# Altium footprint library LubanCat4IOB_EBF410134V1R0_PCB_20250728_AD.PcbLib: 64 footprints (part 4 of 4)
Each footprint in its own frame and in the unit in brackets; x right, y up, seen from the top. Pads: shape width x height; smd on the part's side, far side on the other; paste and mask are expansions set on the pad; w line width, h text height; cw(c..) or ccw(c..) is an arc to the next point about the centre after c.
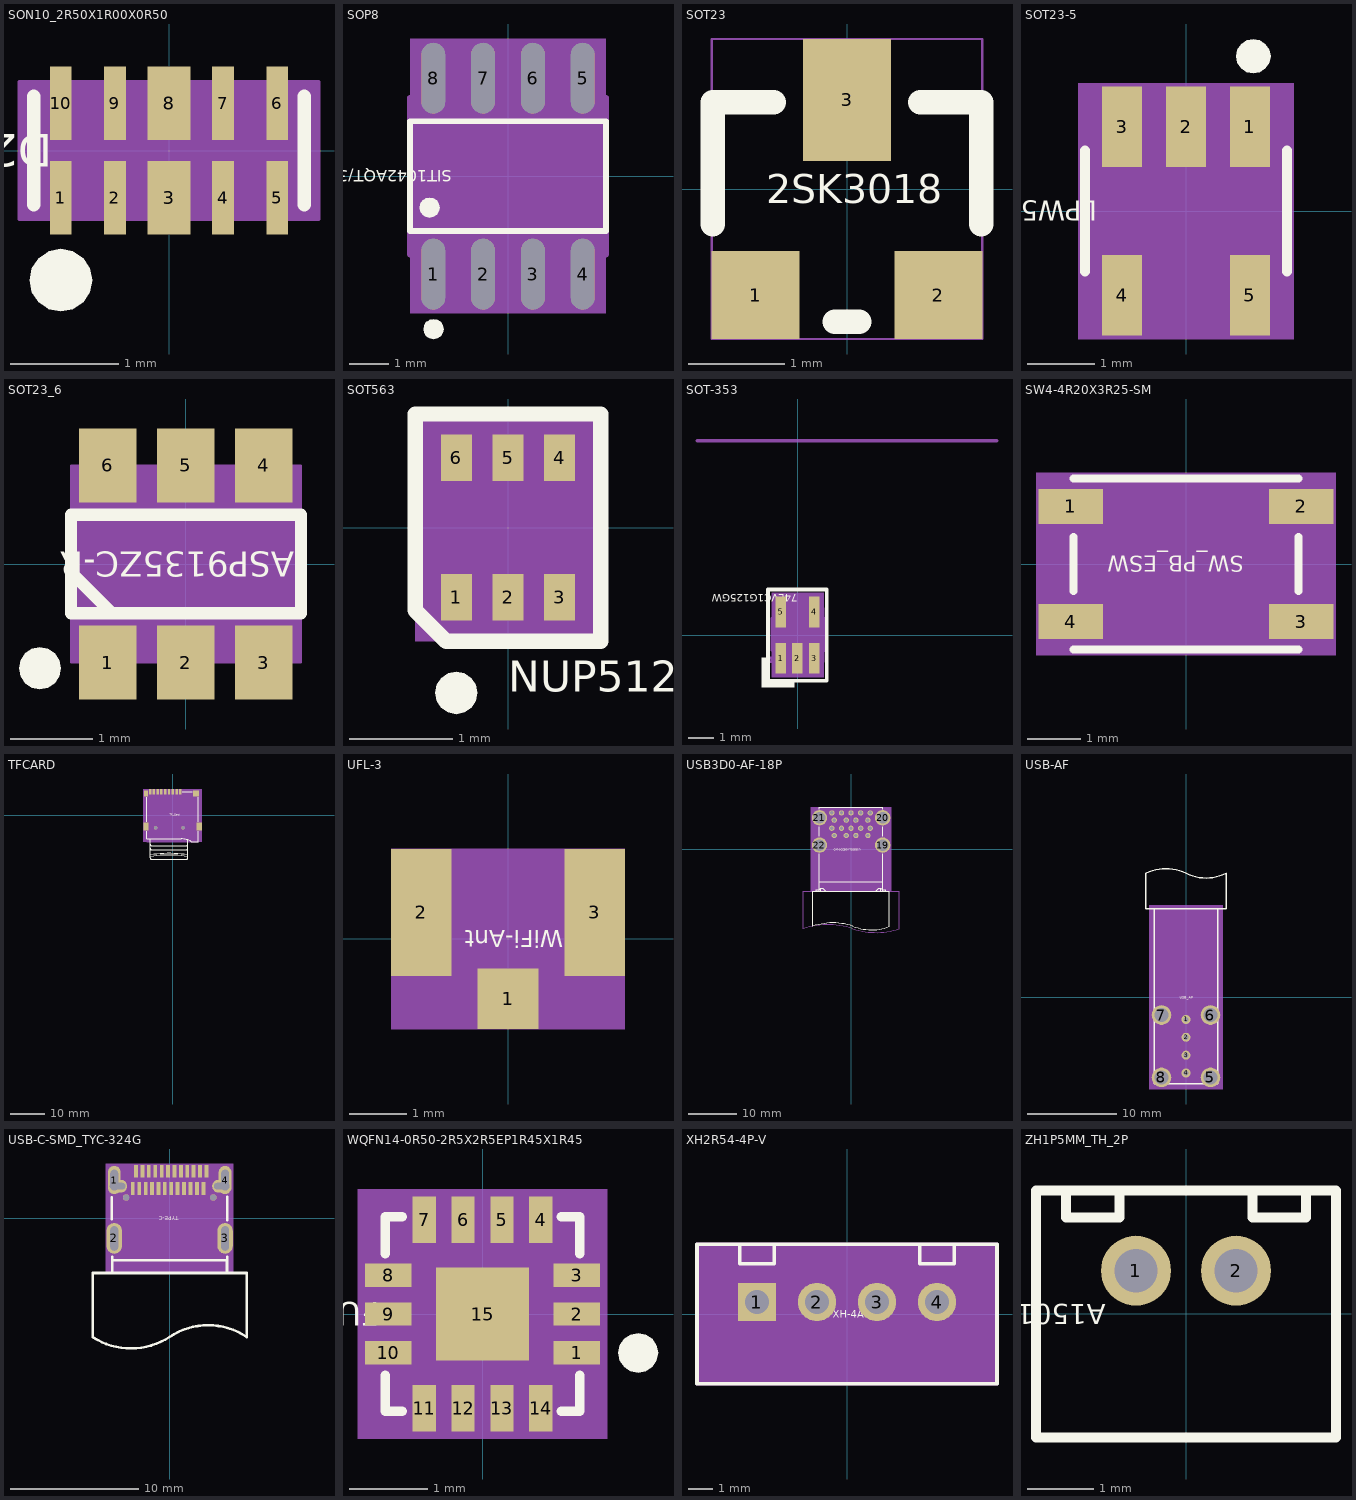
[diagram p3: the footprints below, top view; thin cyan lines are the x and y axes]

## SON10_2R50X1R00X0R50 [mm] "SON10_2R50X1R00X0R50"
pads (10):
  rect 0.2x0.68 smd: 1(-1,-0.437) 2(-0.5,-0.437) 4(0.5,-0.437) 5(1,-0.437) 6(1,0.437) 7(0.5,0.437) 9(-0.5,0.437) 10(-1,0.437)
  rect 0.4x0.68 smd: 3(0,-0.437) 8(0,0.437)
Top Overlay:
  dashed: -0.71,-1.199 -0.733,-1.31 -0.795,-1.404 -0.889,-1.467 -1,-1.489 -1.111,-1.467 -1.142,-1.446 -1.205,-1.404 -1.267,-1.31 -1.29,-1.199 -1.267,-1.089 -1.205,-0.995 -1.142,-0.953 -1.111,-0.932 -1,-0.91 -0.889,-0.932 -0.795,-0.995 -0.733,-1.089
  lines w0.127: -1.25,-0.5 -1.25,0.5 ; 1.25,-0.5 1.25,0.5
  text "D2550-3R3" at -1.08,0.15 h0.3
Top 3D Body:
  region: -1.388,-0.638 -1.388,0.638 1.388,0.638 1.388,-0.638
Mechanical 17:
  text "6" at 0.939,0.437 h0.15
  text "5" at 0.939,-0.437 h0.15
  text "4" at 0.439,-0.437 h0.15
  text "7" at 0.439,0.437 h0.15
  text "2" at -0.561,-0.437 h0.15
  text "9" at -0.561,0.437 h0.15
  text "1" at -1.061,-0.437 h0.15
  text "10" at -1.122,0.437 h0.15
  text "3" at -0.061,-0.437 h0.15
  text "8" at -0.061,0.437 h0.15
Top Assembly:
  lines w0.025: -1.388,-0.638 -1.388,0.638 1.388,0.638 1.388,-0.638 -1.388,-0.638
3D body: height 3.81, standoff 0, extent -1.388,-0.638 1.388,0.638

## SOP8 [mm] "SOP8"
pads (8):
  oval 0.6x1.8 smd: 1(-1.905,-2.5) 2(-0.635,-2.5) 3(0.635,-2.5) 4(1.905,-2.5) 5(1.905,2.5) 6(0.635,2.5) 7(-0.635,2.5) 8(-1.905,2.5)
Top Overlay:
  dashed: -1.645,-3.9 -1.665,-3.998 -1.72,-4.08 -1.802,-4.135 -1.9,-4.155 -1.998,-4.135 -2.025,-4.117 -2.08,-4.08 -2.135,-3.998 -2.155,-3.9 -2.135,-3.802 -2.08,-3.72 -2.025,-3.683 -1.998,-3.665 -1.9,-3.645 -1.802,-3.665 -1.72,-3.72 -1.665,-3.802
  dashed: -1.745,-0.8 -1.765,-0.898 -1.82,-0.98 -1.902,-1.035 -2,-1.055 -2.098,-1.035 -2.125,-1.017 -2.18,-0.98 -2.235,-0.898 -2.255,-0.8 -2.235,-0.702 -2.18,-0.62 -2.125,-0.583 -2.098,-0.565 -2,-0.545 -1.902,-0.565 -1.82,-0.62 -1.765,-0.702
  lines w0.15: -2.5,-1.4 2.5,-1.4 2.5,1.4 -2.5,1.4 -2.5,-1.4
  text "SIT1042AQT/3" at -1.44,0.15 h0.3
Top 3D Body:
  region: -2.5,3.5 -2.5,-3.5 2.5,-3.5 2.5,3.5
Mechanical 17:
  text "4" at 1.651,-2.5 h0.64
  text "1" at -2.159,-2.5 h0.64
  text "5" at 1.651,2.5 h0.64
  text "6" at 0.381,2.5 h0.64
  text "7" at -0.889,2.5 h0.64
  text "3" at 0.381,-2.5 h0.64
  text "2" at -0.889,-2.5 h0.64
  text "8" at -2.159,2.5 h0.64
Top Assembly:
  lines w0.15: -2.5,-2 2.5,-2 2.5,2 -2.5,2 -2.5,-2
3D body: height 3.81, standoff 0, extent -2.5,-3.5 2.5,3.5

## SOT23 [mil] "SOT23"
pads (3):
  rect 36x36 smd: 1(-37.5,-43.5) 2(37.5,-43.5)
  rect 36x50 smd: 3(0,36.5)
Top Overlay:
  lines w10: -55,-14.5 -55,35.5 -30,35.5 ; -5,-54.5 5,-54.5 ; 30,35.5 55,35.5 55,-14.5
  text "2SK3018" at -33.07,-5.91 h11.81
Top 3D Body:
  lines w1: -55.5,-61.5 55.5,-61.5 55.5,61.5 -55.5,61.5 -55.5,-61.5
Mechanical 17:
  text "3" at -18,36.5 h45
  text "1" at -55.5,-43.5 h45
  text "2" at 19.5,-43.5 h45

## SOT23-5 [mm] "SOT23-5"
pads (5):
  rect 0.599x1.199 smd: 1(0.95,1.25) 2(0,1.25) 3(-0.95,1.25) 4(-0.95,-1.25) 5(0.95,-1.25)
Top Overlay:
  dashed: 1.255,2.3 1.235,2.202 1.18,2.12 1.098,2.065 1,2.045 0.902,2.065 0.875,2.083 0.82,2.12 0.765,2.202 0.745,2.3 0.765,2.398 0.82,2.48 0.875,2.517 0.902,2.535 1,2.555 1.098,2.535 1.18,2.48 1.235,2.398
  lines w0.15: -1.5,-0.9 -1.5,0.9 ; 1.5,-0.9 1.5,0.9
  text "LPW5209AB5F" at -1.32,0.15 h0.3
Top 3D Body:
  region: 1.6,-1.9 1.6,1.9 -1.6,1.9 -1.6,-1.9
Mechanical 17:
  text "1" at 0.91,1.25 h0.1
  text "3" at -0.99,1.25 h0.1
  text "4" at -0.99,-1.25 h0.1
  text "2" at -0.04,1.25 h0.1
  text "5" at 0.91,-1.25 h0.1
Top Assembly:
  lines w0.15: -1.5,-0.85 -1.5,0.85 1.5,0.85 1.5,-0.85 -1.5,-0.85
3D body: height 3.81, standoff 0, extent -1.6,-1.9 1.6,1.9

## SOT23_6 [mm] "SOT23_6"
pads (6):
  rect 0.7x0.9 smd: 1(-0.95,-1.2) 2(0,-1.2) 3(0.95,-1.2) 4(0.95,1.2) 5(0,1.2) 6(-0.95,1.2)
Top Overlay:
  dashed: -2.033,-1.27 -2.014,-1.368 -1.958,-1.45 -1.876,-1.506 -1.778,-1.525 -1.68,-1.506 -1.653,-1.487 -1.598,-1.45 -1.542,-1.368 -1.523,-1.27 -1.542,-1.172 -1.598,-1.09 -1.653,-1.053 -1.68,-1.034 -1.778,-1.015 -1.876,-1.034 -1.958,-1.09 -2.014,-1.172
  lines w0.15: -1.4,-0.1 -0.9,-0.6 ; -1.4,-0.6 -1.4,0.6 1.4,0.6 1.4,-0.6 -1.4,-0.6
  text "ASP9135ZC-R" at 1.32,0.15 h0.3
Top 3D Body:
  region: -1.4,-1.2 1.4,-1.2 1.4,1.2 -1.4,1.2
Mechanical 17:
  text "4" at 1.204,1.2 h0.64
  text "6" at -0.696,1.2 h0.64
  text "5" at 0.254,1.2 h0.64
  text "2" at 0.254,-1.2 h0.64
  text "3" at 1.204,-1.2 h0.64
  text "1" at -0.696,-1.2 h0.64
Top Assembly:
  lines w0.025: -1.4,-1.2 1.4,-1.2 1.4,1.2 -1.4,1.2 -1.4,-1.2
3D body: height 3.81, standoff 0, extent -1.4,-1.2 1.4,1.2

## SOT563 [mm] "SOT563"
pads (6):
  rect 0.3x0.45 smd: 1(-0.5,-0.675) 2(0,-0.675) 3(0.5,-0.675) 4(0.5,0.675) 5(0,0.675) 6(-0.5,0.675)
Top Overlay:
  dashed: -0.5,-1.396 -0.422,-1.412 -0.356,-1.456 -0.312,-1.522 -0.296,-1.6 -0.312,-1.678 -0.326,-1.7 -0.356,-1.744 -0.422,-1.788 -0.5,-1.804 -0.578,-1.788 -0.644,-1.744 -0.674,-1.7 -0.688,-1.678 -0.704,-1.6 -0.688,-1.522 -0.644,-1.456 -0.578,-1.412
  lines w0.15: -0.9,-0.8 -0.6,-1.1 0.9,-1.1 0.9,1.1 -0.8,1.1 -0.9,1.1 -0.9,-0.8
  text "NUP5120X6T1G" at 0,-1.59 h0.3
Top 3D Body:
  region: -0.9,1.1 -0.9,-1.1 0.9,-1.1 0.9,1.1
Mechanical 17:
  text "1" at -0.4,-1.015 h0.3
  text "4" at 0.6,0.335 h0.3
  text "6" at -0.4,0.335 h0.3
  text "5" at 0.1,0.335 h0.3
  text "2" at 0.1,-1.015 h0.3
  text "3" at 0.6,-1.015 h0.3
Top Assembly:
  lines w0.15: -0.75,-0.55 0.75,-0.55 0.75,0.55 -0.75,0.55 -0.75,-0.55
3D body: height 3.81, standoff 0, extent -0.9,-1.1 0.9,1.1

## SOT-353 [mil] "SOT-353"
pads (5):
  rect 16x47 smd: 1(-25.91,-35.43) 2(-0.32,-35.43) 3(25.28,-35.43) 4(25.28,35.43) 5(-25.91,35.43)
Top Overlay:
  dashed: -45.31,-35 -55.31,-35 -55.31,-80 -5.32,-80 -5.32,-70 -45.31,-70
  lines w6: -45.31,-70 44.69,-70 44.69,70 -45.31,70 -45.31,-70
  text "74LVC1G125GW" at -0.01,62.6 h11.81
  text ".Designator" at -110,24 h30
Top Courtyard:
  dashed: -39.69,-65 39.69,-65 39.69,65 -39.69,65
Top 3D Body:
  region: -39.69,-65 39.69,-65 39.69,65 -39.69,65
Top Component Center:
  circle w1: c-0.32,0 r11.81
  circle w1: c-0.32,0 r11.81
  lines w1: -16.06,0 15.43,0 -16.06,0 ; -0.32,-15.75 -0.32,15.75 -0.32,-15.75
Mechanical 17:
  text "4" at 25.28,41.83 h16
  text "2" at -0.32,-29.03 h16
  text "5" at -25.91,41.83 h16
  text "3" at 25.28,-29.03 h16
  text "1" at -25.91,-29.03 h16
Top Assembly:
  circle w3.94: c-41.31,-38 r2.83
  lines w3.94: -32.31,-24 -32.31,-40.83 -20.32,-40.83 ; -31.5,26 -31.5,40.83 ; -31.5,41.83 -19.5,41.83 -19.5,26 ; -20.32,-40 -20.32,-25 ; -6.32,-24 -6.32,-40.83 5.68,-40.83 ; 5.68,-40 5.68,-24 ; 19.68,-24 19.68,-40.83 31.68,-40.83 ; 19.68,26 19.68,41 ; 19.68,41.83 31.68,41.83 31.68,26 ; 31.68,-40 31.68,-24 ; -39.31,-23.61 40.69,-23.61 40.69,25.61 -39.31,25.61 -39.31,-23.61
Mechanical 22:
  lines w5: -154.31,298 305.69,298
  text "Remark: ***" at -124.31,98 h25
  text "Rev   : A1" at -124.31,138 h25
  text "Date  : 2007-11-30" at -124.31,178 h25
  text "Creat : Yuki" at -124.31,218 h25
  text "Ref PN: ESDALC6V1W5" at -124.31,258 h25
  text "Sofer Lib Information" at -154.31,308 h25
Mechanical 23:
  lines w1: -39.31,-41 -39.31,42 40.69,42 40.69,-41 -39.31,-41
Mechanical 24:
  text "Approved" at -0.32,112 h35
Mechanical 25:
  text "SOT-353" at 4.68,-79 h30
3D body: height 150, standoff 0, extent -39.69,-65 39.69,65

## SW4-4R20X3R25-SM [mm] "SW4-4R20X3R25-SM"
pads (4):
  rect 1.2x0.65 smd: 1(-2.15,1.075) 2(2.15,1.075) 3(2.15,-1.075) 4(-2.15,-1.075)
Top Overlay:
  lines w0.15: -2.1,-1.6 2.1,-1.6 ; -2.1,-0.5 -2.1,0.5 ; -2.1,1.6 2.1,1.6 ; 2.1,-0.5 2.1,0.5
  text "SW_PB_ESW" at 1.08,0.15 h0.3
Top 3D Body:
  region: -2.8,1.7 -2.8,-1.7 2.8,-1.7 2.8,1.7
Mechanical 17:
  text "4" at -1.592,-1.2 h0.64
  text "3" at 2.608,-1.2 h0.64
  text "2" at 2.608,0.9 h0.64
  text "1" at -1.592,1 h0.64
Top Assembly:
  lines w0.15: -2.1,-1.625 2.1,-1.625 2.1,1.625 -2.1,1.625 -2.1,-1.625
3D body: height 3.81, standoff 0, extent -2.8,-1.7 2.8,1.7

## TFCARD [mm] "TFCARD"
pads (15):
  rect 0.7x1.6 smd: 1(2.25,6.85) 2(1.15,6.85) 3(0.05,6.85) 4(-1.05,6.85) 5(-2.15,6.85) 6(-3.25,6.85) 7(-4.35,6.85) 8(-5.45,6.85) 9(-6.55,6.85)
  rect 1.2x1.778 smd: 10(-7.75,6.35)
  rect 1.524x2.413 smd: 11(-7.75,-3.25) 12(7.75,-3.25)
  rect 1.778x1.778 smd: 13(6.85,6.35)
  round 1 hole 1 unplated: ""(-4.95,-3.65) ""(3.05,-3.65)
Top Overlay:
  lines w0.1: -6.55,-12.05 cw(c-1.05,-45.613) 4.45,-12.05 ; -6.55,-11.55 cw(c-1.05,-45.113) 4.45,-11.55
  lines w0.15: -7.45,-4.65 -7.45,-6.85 2.45,-6.85 cw(c2.37,-13.175) 5.45,-7.65 7.45,-7.65 7.45,-4.65 ; -7.45,-1.85 -7.45,5.25 ; -6.55,-9.35 -6.55,-12.35 ccw(c-6.05,-12.35) -6.05,-12.85 3.95,-12.85 ccw(c3.95,-12.35) 4.45,-12.35 4.45,-9.55 ; -6.55,-6.85 -6.55,-8.35 ; 2.85,6.85 5.75,6.85 ; 4.45,-7.25 4.45,-7.65 4.45,-8.35 ; 7.45,-1.85 7.45,5.25 ; -6.55,-8.35 ccw(c-6.05,-8.35) -6.05,-8.85 3.95,-8.85 ccw(c3.95,-8.35) 4.45,-8.35 ; -6.55,-8.35 -6.55,-9.55 ccw(c-6.05,-9.55) -6.05,-10.05 3.95,-10.05 ccw(c3.95,-9.55) 4.45,-9.55 ; 4.45,-9.55 4.45,-8.35
  text "TF_Card" at -0.84,-0.15 h0.3
Top 3D Body:
  region: -8.512,-7.65 8.512,-7.65 8.512,7.65 -8.512,7.65
Mechanical 17:
  text "4" at -1.355,6.85 h0.76
  text "9" at -6.855,6.85 h0.76
  text "3" at -0.255,6.85 h0.76
  text "1" at 1.945,6.85 h0.76
  text "8" at -5.755,6.85 h0.76
  text "7" at -4.655,6.85 h0.76
  text "2" at 0.845,6.85 h0.76
  text "5" at -2.455,6.85 h0.76
  text "12" at 7.14,-3.25 h0.76
  text "6" at -3.555,6.85 h0.76
  text "13" at 6.24,6.35 h0.76
  text "10" at -8.36,6.35 h0.76
  text "11" at -8.36,-3.25 h0.76
Top Assembly:
  lines w0.15: -7.45,-7.65 7.45,-7.65 7.45,6.85 7.35,6.85 -7.45,6.85 -7.45,-7.65
3D body: height 3.81, standoff 0, extent -8.512,-7.65 8.512,7.65

## UFL-3 [mm] "UFL-3"
pads (3):
  rect 1.05x1.05 smd: 1(0,-1.038)
  rect 1.05x2.2 smd: 2(-1.5,0.462) 3(1.5,0.462)
Top Overlay:
  text "WiFi-Ant" at 0.96,0.15 h0.3
Top 3D Body:
  region: -2.025,-1.562 2.025,-1.562 2.025,1.562 -2.025,1.562
Mechanical 17:
  text "1" at 0.305,-1.038 h0.76
  text "2" at -1.195,0.462 h0.76
  text "3" at 1.805,0.462 h0.76
3D body: height 3.81, standoff 0, extent -2.025,-1.562 2.025,1.562

## USB3D0-AF-18P [mm] "USB3D0-AF-18P"
pads (22):
  round 1.1 / inner round 1.524 / far side round 1.1 hole 0.7: 1(-3.5,2.899) 2(-1.001,2.899) 3(1.001,2.899) 5(4,4.401) 6(1.999,4.401) 8(-1.999,4.401) 9(-4,4.401) 10(-3.5,6.1) 11(-1.001,6.1) 12(1.001,6.1) 14(4,7.601) 15(1.999,7.601) 17(-1.999,7.601) 18(-4,7.601)
  round 1.1 hole 0.7: 4(3.5,2.899) 7(0,4.401) 13(3.5,6.1) 16(0,7.601)
  round 3.2 hole 2.4: 19(6.571,0.9) 20(6.571,6.58) 21(-6.571,6.58) 22(-6.571,0.9)
Top Overlay:
  lines w0.15: -7.257,-8.719 -6.284,-8.719 -6.284,-8.091 -5.86,-8.091 -5.235,-8.719 5.067,-8.719 ; -7.257,-8.388 -6.617,-8.388 -6.284,-8.056 ; -6.571,-0.931 -6.571,-3.299 -6.571,-4.379 -6.571,-8.719 -6.571,-6.719 6.571,-6.719 6.571,-8.719 6.571,-4.879 6.571,-3.999 6.571,-0.931 ; -6.571,2.732 -6.571,4.749 ; -6.571,8.411 -6.571,8.774 6.571,8.774 6.571,8.411 ; 5.169,-8.719 5.796,-8.091 6.218,-8.091 6.218,-8.719 7.193,-8.719 ; 6.218,-8.056 6.551,-8.388 7.193,-8.388 ; 6.571,2.732 6.571,4.749 ; -8,-16.019 cw(c-3.773,-28.033) 0.4,-15.999 ccw(c4.224,-6.389) 8,-16.019 8,-8.719 0,-8.719 -8,-8.719 -8,-16.019
  lines w0.254: -7.257,-8.719 -7.257,-8.388 ; 7.193,-8.719 7.193,-8.388
  text "USB3D0_USB2D0-A-D" at 2.04,0.15 h0.3
Bottom Overlay:
  drawing of 19 lines, arcs and shapes, not listed
Top 3D Body:
  region: -8.4,8.8 -8.4,-8.8 8.4,-8.8 8.4,8.8
Mechanical 17:
  text "10" at -2.992,6.1 h0.64
  text "1" at -3.246,2.899 h0.64
  text "14" at 4.508,7.601 h0.64
  text "15" at 2.507,7.601 h0.64
  text "17" at -1.491,7.601 h0.64
  text "18" at -3.492,7.601 h0.64
  text "11" at -0.493,6.1 h0.64
  text "2" at -0.747,2.899 h0.64
  text "12" at 1.509,6.1 h0.64
  text "3" at 1.255,2.899 h0.64
  text "8" at -1.745,4.401 h0.64
  text "9" at -3.746,4.401 h0.64
  text "5" at 4.255,4.401 h0.64
  text "6" at 2.253,4.401 h0.64
  text "4" at 3.754,2.899 h0.64
  text "20" at 7.079,6.58 h0.64
  text "22" at -6.063,0.9 h0.64
  text "21" at -6.063,6.58 h0.64
  text "7" at 0.254,4.401 h0.64
  text "13" at 4.008,6.1 h0.64
  text "16" at 0.508,7.601 h0.64
  text "19" at 7.079,0.9 h0.64
Top Assembly:
  lines w0.15: -10,-16.519 cw(c-4.77,-32.788) 0.4,-16.499 ccw(c5.228,-2.363) 10,-16.519 10,-8.719 0,-8.719 -10,-8.719 -10,-16.519
3D body: height 3.81, standoff 0, extent -8.4,-8.8 8.4,8.8

## USB-AF [mm] "USB-AF"
pads (8):
  round 1 / inner round 1.524 / far side round 1 hole 0.6: 1(0,-2.498) 2(0,-4.5) 3(0,-6.502)
  round 1 hole 0.6: 4(0,-8.504)
  round 2.2 hole 1.6: 5(2.749,-9) 6(2.749,-2) 7(-2.751,-2) 8(-2.751,-9)
Top Overlay:
  lines w0.15: -4.5,9.9 -4.5,13.9 cw(c-2.25,9.435) 0,13.9 ccw(c2.25,18.365) 4.5,13.9 4.5,9.9 -4.5,9.9 ; -3.55,-9.7 3.55,-9.7 3.55,9.9 -3.55,9.9 -3.55,-9.7
  text "USB_AF" at -0.72,-0.15 h0.3
Top 3D Body:
  region: -4.1,-10.3 -4.1,10.3 4.1,10.3 4.1,-10.3
Mechanical 17:
  text "1" at -0.24,-2.498 h0.3
  text "2" at -0.24,-4.5 h0.3
  text "3" at -0.24,-6.502 h0.3
  text "6" at 2.509,-2 h0.3
  text "5" at 2.509,-9 h0.3
  text "7" at -2.991,-2 h0.3
  text "4" at -0.24,-8.504 h0.3
  text "8" at -2.991,-9 h0.3
Top Assembly:
  lines w0.025: -3.55,-9.7 -3.55,9.9 3.55,9.9 3.55,-9.7 -3.55,-9.7
3D body: height 3.81, standoff 0, extent -4.1,-10.3 4.1,10.3

## USB-C-SMD_TYC-324G [mm] "USB-C-SMD_TYC-324G"
pads (32):
  oval 1x2.2 / inner round 1.524 / far side oval 1x2.2 hole 1.6 slot 0.6 at 0 deg: 1(-4.32,2.99) 4(4.32,2.99)
  oval 1.2x2.4 / inner round 1.524 / far side oval 1.2x2.4 hole 1.9 slot 0.6 at 0 deg: 2(-4.32,-1.56) 3(4.32,-1.56)
  rect 0.3x1 smd: A1(-2.62,3.68) A2(-2.13,3.68) A3(-1.63,3.68) A4(-1.13,3.68) A5(-0.62,3.68) A6(-0.12,3.68) A7(0.38,3.68) A8(0.88,3.68) A9(1.37,3.68) A10(1.87,3.68) A11(2.37,3.68) A12(2.88,3.68) B1(2.63,2.34) B2(2.13,2.34) B3(1.63,2.34) B4(1.13,2.34) B5(0.62,2.34) B6(0.12,2.34) B7(-0.38,2.34) B8(-0.87,2.34) B9(-1.37,2.34) B10(-1.87,2.34) B11(-2.37,2.34) B12(-2.88,2.34)
  oval 1.5x1 hole 0.5 slot 1.2 at 0 deg: ""(-4.06,2.51) ""(4.06,2.51)
  round 0.5 hole 0.5 unplated: ""(-3.4,1.63) ""(3.4,1.63)
Top Overlay:
  lines w0.2: -4.5,-0.06 -4.5,1.65 ; -4.47,-3 -4.47,-3.26 ; 4.5,-2.98 4.5,-4.24 4.47,-4.26 ; 4.5,-0.14 4.5,1.67 ; 6,-9.26 6,-4.26 -6,-4.26 -6,-9.26 ccw(c-3.015,-4.643) 0,-9.24 cw(c3,-13.74) 6,-9.24 ; -4.47,-3.26 4.47,-3.26 4.47,-4.26 ; -4.47,-3.26 -4.47,-4.26 4.47,-4.26
  text "TYPE-C" at 0.72,0.15 h0.3
Top 3D Body:
  region: -4.97,-4.24 4.97,-4.24 4.97,4.24 -4.97,4.24
Mechanical 17:
  text "A10" at 1.99,3.68 h0.1
  text "B10" at -1.75,2.34 h0.1
  text "B3" at 1.71,2.34 h0.1
  text "A3" at -1.55,3.68 h0.1
  text "B2" at 2.21,2.34 h0.1
  text "A11" at 2.49,3.68 h0.1
  text "B11" at -2.25,2.34 h0.1
  text "A2" at -2.05,3.68 h0.1
  text "B5" at 0.7,2.34 h0.1
  text "A5" at -0.54,3.68 h0.1
  text "3" at 4.36,-1.56 h0.1
  text "4" at 4.36,2.99 h0.1
  text "2" at -4.28,-1.56 h0.1
  text "1" at -4.28,2.99 h0.1
  text "A4" at -1.05,3.68 h0.1
  text "B9" at -1.29,2.34 h0.1
  text "B4" at 1.21,2.34 h0.1
  text "A9" at 1.45,3.68 h0.1
  text "A7" at 0.46,3.68 h0.1
  text "B7" at -0.3,2.34 h0.1
  text "A6" at -0.04,3.68 h0.1
  text "B6" at 0.2,2.34 h0.1
  text "B8" at -0.79,2.34 h0.1
  text "A8" at 0.96,3.68 h0.1
  text "A12" at 3,3.68 h0.1
  text "B1" at 2.71,2.34 h0.1
  text "A1" at -2.54,3.68 h0.1
  text "B12" at -2.76,2.34 h0.1
3D body: height 3.81, standoff 0, extent -4.97,-4.24 4.97,4.24

## WQFN14-0R50-2R5X2R5EP1R45X1R45 [mm] "WQFN14-0R50-2R5X2R5EP1R45X1R45"
pads (15):
  rect 0.6x0.3 smd: 1(1.21,-0.5) 2(1.21,0) 3(1.21,0.5) 8(-1.21,0.5) 9(-1.21,0) 10(-1.21,-0.5)
  rect 0.3x0.6 smd: 4(0.75,1.21) 5(0.25,1.21) 6(-0.25,1.21) 7(-0.75,1.21) 11(-0.75,-1.21) 12(-0.25,-1.21) 13(0.25,-1.21) 14(0.75,-1.21)
  rect 1.2x1.2 smd: 15(0,0)
Top Overlay:
  dashed: 2.255,-0.5 2.235,-0.598 2.18,-0.68 2.098,-0.735 2,-0.755 1.902,-0.735 1.875,-0.717 1.82,-0.68 1.765,-0.598 1.745,-0.5 1.765,-0.402 1.82,-0.32 1.875,-0.283 1.902,-0.265 2,-0.245 2.098,-0.265 2.18,-0.32 2.235,-0.402
  lines w0.127: -1.25,-0.789 -1.25,-1.25 -1.034,-1.25 ; -1.25,0.777 -1.25,1.25 -1.034,1.25 ; 1.016,-1.25 1.25,-1.25 1.25,-0.789 ; 1.016,1.25 1.25,1.25 1.25,0.777
  text "FUSB302BMPX" at -1.32,0.15 h0.3
Top 3D Body:
  region: 1.6,-1.6 1.6,1.6 -1.6,1.6 -1.6,-1.6
Mechanical 17:
  text "7" at -0.79,1.21 h0.1
  text "6" at -0.29,1.21 h0.1
  text "14" at 0.67,-1.21 h0.1
  text "1" at 1.17,-0.5 h0.1
  text "11" at -0.83,-1.21 h0.1
  text "10" at -1.29,-0.5 h0.1
  text "2" at 1.17,0 h0.1
  text "5" at 0.21,1.21 h0.1
  text "4" at 0.71,1.21 h0.1
  text "3" at 1.17,0.5 h0.1
  text "8" at -1.25,0.5 h0.1
  text "15" at -0.08,0 h0.1
  text "9" at -1.25,0 h0.1
  text "13" at 0.17,-1.21 h0.1
  text "12" at -0.33,-1.21 h0.1
Top Assembly:
  lines w0.025: -1.51,-1.36 1.51,-1.36 1.51,1.36 -1.51,1.36 -1.51,-1.36
3D body: height 3.81, standoff 0, extent -1.6,-1.6 1.6,1.6

## XH2R54-4P-V [mm] "XH2R54-4P-V"
pads (4):
  rect 1.6x1.6 / inner round 1.524 / far side rect 1.6x1.6 hole 1: 1(-3.75,0.5)
  round 1.6 / inner round 1.524 / far side round 1.6 hole 1: 2(-1.25,0.5) 3(1.25,0.5)
  round 1.6 hole 1: 4(3.75,0.5)
Top Overlay:
  lines w0.152: -6.25,-2.9 6.25,-2.9 6.25,2.9 -6.25,2.9 -6.25,-2.9 ; -4.47,2.1 -4.47,2.9 -3.03,2.9 -3.03,2.1 -4.47,2.1 ; 3.03,2.1 3.03,2.9 4.47,2.9 4.47,2.1 3.03,2.1
  text "XH-4A" at -0.6,-0.15 h0.3
Bottom Overlay:
  lines w0.5: -2.5,-0.22 -2.5,1.22 ; 0,-0.22 0,1.22 ; 2.5,-0.22 2.5,1.22
Top 3D Body:
  region: -6.25,2.9 -6.25,-2.9 6.25,-2.9 6.25,2.9
Mechanical 17:
  text "2" at -1.504,0.5 h0.64
  text "3" at 0.996,0.5 h0.64
  text "4" at 3.496,0.5 h0.64
  text "1" at -4.004,0.5 h0.64
Top Assembly:
  lines w0.152: -6.25,-2.9 6.25,-2.9 6.25,2.9 -6.25,2.9 -6.25,-2.9
3D body: height 3.81, standoff 0, extent -6.25,-2.9 6.25,2.9

## ZH1P5MM_TH_2P [mm] "ZH1P5MM_TH_2P"
pads (2):
  round 1.05 / inner round 1.524 / far side round 1.05 hole 0.65: 1(-0.75,0.65)
  round 1.05 hole 0.65: 2(0.75,0.65)
Top Overlay:
  lines w0.15: -1.8,1.85 -1.8,1.45 -1,1.45 -1,1.85 ; 1,1.85 1,1.45 1.8,1.45 1.8,1.85 ; -2.25,-1.85 2.25,-1.85 2.25,1.85 -2.25,1.85 -2.25,-1.85
  text "A1501WV-2P" at -1.2,0.15 h0.3
Bottom Overlay:
  lines w0.3: 0,-0.15 0,1.45 ; -1.5,-0.15 -1.5,1.45 1.5,1.45 1.5,-0.15 -1.3,-0.15 -1.5,-0.15
Top 3D Body:
  lines w0.025: -2.2,-1.85 2.2,-1.85 2.2,1.85 -2.2,1.85 -2.2,-1.85
Mechanical 17:
  text "1" at -1.065,0.65 h0.79
  text "2" at 0.435,0.65 h0.79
